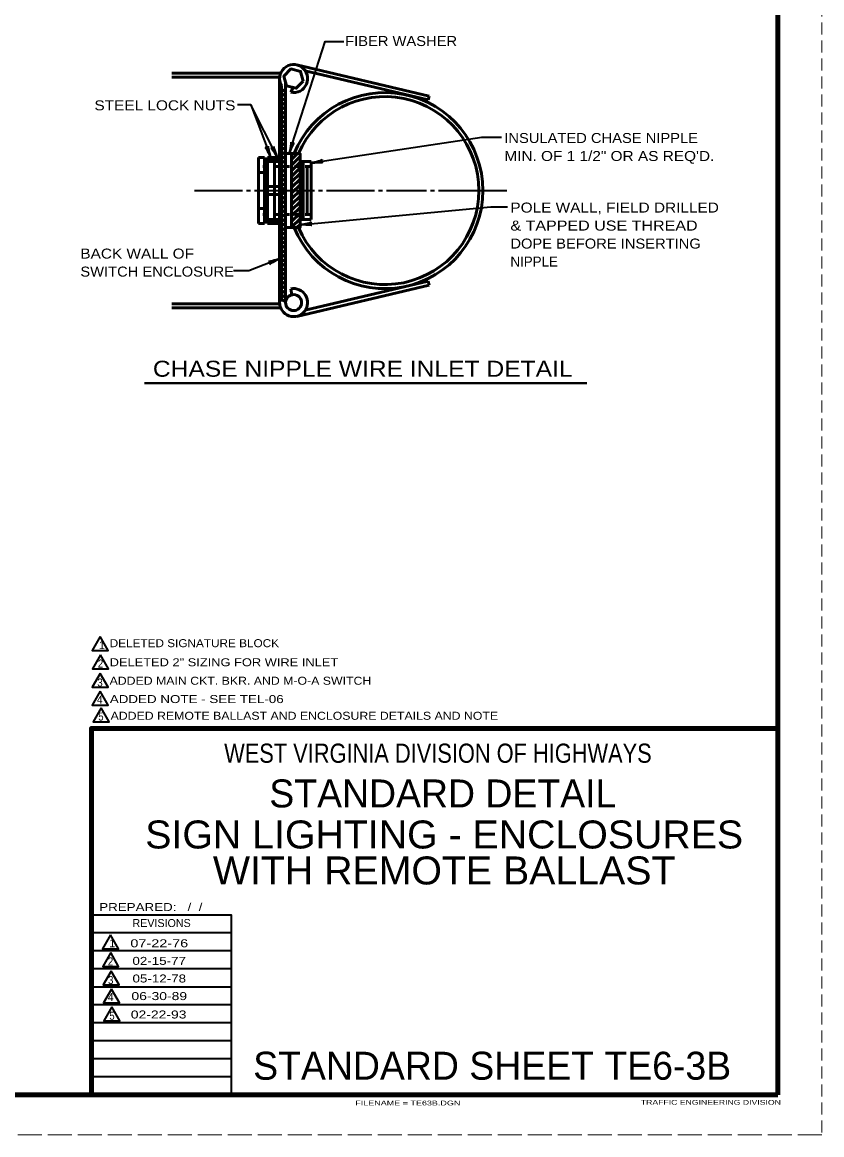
# Model space of a CAD drawing. Extents: x -77 to 603, y -47 to 393.
# Drawn here: x 403.1 to 603.1, y -46.8 to 231.3 of the extents above; entities that cross this region are included whole.
import ezdxf
from ezdxf.enums import TextEntityAlignment as Align

# ---------------------------------------------------------------- set-up
doc = ezdxf.new("R2010")
doc.units = 0
for name, pattern in [('LONG_DASHED', [7.5, 6, -1.5]), ('MEDIUM_DASHED', [4.5, 3, -1.5]), ('SHORT_DASHED', [2.7, 1.5, -1.2])]:
    doc.linetypes.add(name, pattern=pattern)
doc.layers.add('1', color=7, linetype='Continuous', lineweight=53)
doc.layers.add('61', color=7, linetype='Continuous', lineweight=35)

msp = doc.modelspace()

# ---------------------------------------------------------------- linework, layer by layer
at = {"layer": '1', "linetype": 'MEDIUM_DASHED', "lineweight": 13}
msp.add_line((603.055, 393.264), (603.035, -46.756), dxfattribs=at)
at = {"layer": '1'}
for p, q in [((471.839, 220.696), (504.888, 212.859)), ((467.758, 218.556), (440.517, 218.556)), ((467.517, 217.556), (440.517, 217.556)), ((467.502, 217.242), (467.502, 161.242)), ((473.92, 219.174), (504.657, 211.886)), ((467.502, 214.026), (468.002, 214.526)), ((468.002, 215.439), (468.002, 161.977)), ((468.002, 214.526), (469.002, 214.026)), ((469.002, 216.349), (469.002, 161.242)), ((470.283, 213.816), (470.892, 215.033)), ((467.502, 212.93), (468.002, 213.43)), ((467.502, 211.79), (468.002, 212.29)), ((468.002, 213.408), (469.002, 212.908)), ((468.002, 212.29), (469.002, 211.79)), ((504.657, 211.886), (504.888, 212.859)), ((467.502, 210.672), (468.002, 211.172)), ((467.502, 209.554), (468.002, 210.054)), ((467.502, 208.436), (468.002, 208.936)), ((468.002, 211.172), (469.002, 210.672)), ((468.002, 210.054), (469.002, 209.554)), ((468.002, 208.936), (469.002, 208.436)), ((467.502, 207.318), (468.002, 207.818)), ((467.502, 206.2), (468.002, 206.7)), ((468.002, 207.818), (469.002, 207.318)), ((468.002, 206.7), (469.002, 206.2)), ((467.502, 205.082), (468.002, 205.582)), ((467.502, 203.964), (468.002, 204.464)), ((467.502, 202.846), (468.002, 203.346)), ((468.002, 205.582), (469.002, 205.082)), ((468.002, 204.464), (469.002, 203.964)), ((468.002, 203.346), (469.002, 202.845)), ((467.502, 201.727), (468.002, 202.227)), ((467.502, 200.609), (468.002, 201.109)), ((468.002, 202.227), (469.002, 201.727)), ((468.002, 201.109), (469.002, 200.609)), ((462.252, 197.492), (462.252, 180.992)), ((462.252, 197.492), (463.752, 197.492)), ((463.752, 197.492), (463.752, 180.992)), ((467.502, 197.492), (464.502, 197.492)), ((464.502, 197.492), (464.502, 180.992)), ((466.252, 197.492), (466.252, 180.992)), ((467.502, 199.491), (468.002, 199.991)), ((467.502, 198.373), (468.002, 198.873)), ((467.502, 197.255), (468.002, 197.755)), ((468.002, 199.991), (469.002, 199.491)), ((468.002, 198.873), (469.002, 198.373)), ((468.002, 197.755), (469.002, 197.255)), ((470.502, 198.492), (469.002, 198.492)), ((470.502, 198.458), (470.536, 198.492)), ((470.502, 197.044), (471.95, 198.492)), ((470.502, 195.63), (472.627, 197.755)), ((467.502, 196.492), (463.752, 196.492)), ((467.502, 196.992), (464.502, 196.992)), ((467.502, 196.137), (468.002, 196.637)), ((467.502, 195.019), (468.002, 195.519)), ((468.002, 196.637), (469.002, 196.137)), ((468.002, 195.519), (469.002, 195.019)), ((470.502, 194.215), (472.627, 196.34)), ((470.502, 192.801), (472.627, 194.926)), ((475.377, 196.492), (472.627, 196.492)), ((473.377, 196.492), (473.377, 181.992)), ((474.377, 195.242), (474.377, 183.242)), ((475.377, 196.492), (475.377, 181.992)), ((463.752, 193.742), (462.252, 193.742)), ((467.502, 193.901), (468.002, 194.401)), ((467.502, 192.783), (468.002, 193.283)), ((467.502, 191.665), (468.002, 192.165)), ((468.002, 194.401), (469.002, 193.901)), ((468.002, 193.283), (469.002, 192.783)), ((468.002, 192.165), (469.002, 191.665)), ((470.502, 191.387), (472.627, 193.512)), ((470.502, 189.973), (472.627, 192.098)), ((467.502, 190.242), (464.502, 190.242)), ((467.502, 190.547), (468.002, 191.047)), ((467.502, 189.428), (468.002, 189.928)), ((468.002, 191.047), (469.002, 190.546)), ((468.002, 189.928), (469.002, 189.428)), ((470.502, 188.558), (472.627, 190.683)), ((470.502, 187.144), (472.627, 189.269)), ((467.502, 188.242), (464.502, 188.242)), ((467.502, 188.31), (468.002, 188.81)), ((467.502, 187.192), (468.002, 187.692)), ((467.502, 186.074), (468.002, 186.574)), ((468.002, 188.81), (469.002, 188.31)), ((468.002, 187.692), (469.002, 187.192)), ((468.002, 186.574), (469.002, 186.074)), ((470.502, 185.73), (472.627, 187.855)), ((470.502, 184.316), (472.627, 186.441)), ((463.752, 184.742), (462.252, 184.742)), ((467.502, 184.956), (468.002, 185.456)), ((467.502, 183.838), (468.002, 184.338)), ((468.002, 185.456), (469.002, 184.956)), ((468.002, 184.338), (469.002, 183.838)), ((470.502, 182.901), (472.627, 185.026)), ((470.502, 181.487), (472.627, 183.612)), ((462.252, 180.992), (463.752, 180.992)), ((467.502, 181.992), (463.752, 181.992)), ((467.502, 181.492), (464.502, 181.492)), ((467.502, 180.992), (464.502, 180.992)), ((467.502, 182.72), (468.002, 183.22)), ((467.502, 181.602), (468.002, 182.102)), ((467.502, 180.484), (468.002, 180.984)), ((468.002, 183.22), (469.002, 182.72)), ((468.002, 182.102), (469.002, 181.602)), ((468.002, 180.984), (469.002, 180.484)), ((470.502, 180.073), (472.627, 182.198)), ((471.835, 179.992), (472.627, 180.784)), ((475.377, 181.992), (472.627, 181.992)), ((467.502, 179.366), (468.002, 179.866)), ((467.502, 178.248), (468.002, 178.748)), ((468.002, 179.866), (469.002, 179.366)), ((468.002, 178.748), (469.002, 178.248)), ((470.502, 179.992), (469.002, 179.992)), ((467.502, 177.13), (468.002, 177.63)), ((467.502, 176.012), (468.002, 176.512)), ((467.502, 174.893), (468.002, 175.393)), ((468.002, 177.63), (469.002, 177.13)), ((468.002, 176.512), (469.002, 176.011)), ((468.002, 175.393), (469.002, 174.893)), ((467.502, 173.775), (468.002, 174.275)), ((467.502, 172.657), (468.002, 173.157)), ((468.002, 174.275), (469.002, 173.775)), ((468.002, 173.157), (469.002, 172.657)), ((467.502, 171.539), (468.002, 172.039)), ((467.502, 170.421), (468.002, 170.921)), ((467.502, 169.303), (468.002, 169.803)), ((468.002, 172.039), (469.002, 171.539)), ((468.002, 170.921), (469.002, 170.421)), ((468.002, 169.803), (469.002, 169.303)), ((467.502, 168.185), (468.002, 168.685)), ((467.502, 167.067), (468.002, 167.567)), ((468.002, 168.685), (469.002, 168.185)), ((468.002, 167.567), (469.002, 167.067)), ((467.502, 165.949), (468.002, 166.449)), ((467.502, 164.831), (468.002, 165.331)), ((467.502, 163.713), (468.002, 164.213)), ((468.002, 166.449), (469.002, 165.949)), ((468.002, 165.331), (469.002, 164.831)), ((468.002, 164.213), (469.002, 163.713)), ((470.283, 164.667), (470.591, 163.197)), ((471.839, 157.788), (504.888, 165.624)), ((473.92, 159.309), (504.657, 166.597)), ((504.657, 166.597), (504.888, 165.624)), ((467.502, 162.595), (468.002, 163.095)), ((467.502, 161.477), (468.002, 161.977)), ((468.002, 163.095), (469.002, 162.595)), ((468.002, 161.977), (469.002, 161.476)), ((467.517, 160.927), (440.517, 160.927)), ((467.758, 159.927), (440.517, 159.927))]:
    msp.add_line(p, q, dxfattribs=at)
at = {"layer": '1', "lineweight": 35}
for p, q in [((460.33, 210.688), (456.984, 210.688)), ((446.252, 189.242), (458.252, 189.242)), ((459.252, 189.242), (460.252, 189.242)), ((461.252, 189.242), (476.252, 189.242)), ((477.252, 189.242), (478.252, 189.242)), ((479.252, 189.242), (491.252, 189.242)), ((492.252, 189.242), (493.252, 189.242)), ((494.252, 189.242), (504.252, 189.242)), ((505.252, 189.242), (506.252, 189.242)), ((507.252, 189.242), (524.325, 189.242)), ((455.435, 3.664), (420.455, 3.664)), ((455.435, -0.836), (420.455, -0.836)), ((455.435, -5.336), (420.455, -5.336)), ((455.435, -9.856), (420.455, -9.856)), ((455.435, -14.336), (420.455, -14.336)), ((455.435, -18.816), (420.455, -18.816)), ((455.435, -23.316), (420.455, -23.316)), ((455.435, -27.816), (420.455, -27.816)), ((455.435, -32.336), (420.455, -32.336))]:
    msp.add_line(p, q, dxfattribs=at)
at = {"layer": '1', "linetype": 'SHORT_DASHED'}
for p, q in [((467.502, 195.242), (462.252, 195.242)), ((475.377, 195.242), (469.002, 195.242)), ((467.502, 183.242), (462.252, 183.242)), ((475.377, 183.242), (469.002, 183.242))]:
    msp.add_line(p, q, dxfattribs=at)
at = {"layer": '1', "lineweight": 40}
msp.add_line((433.674, 141.075), (544.289, 141.075), dxfattribs=at)
at = {"layer": '1', "lineweight": 35}
for points in [[(469.893, 198.492), (478.882, 226.487), (483.579, 226.487)], [(466.977, 197.492), (460.33, 210.688), (465.281, 197.492)], [(475.377, 196.147), (518.067, 202.582), (522.979, 202.582)], [(472.627, 180.701), (520.289, 185.153), (524.499, 185.153)], [(467.502, 172.204), (459.78, 169.197), (455.931, 169.197)], [(455.435, -36.816), (455.435, 8.144), (420.455, 8.144)]]:
    msp.add_lwpolyline(points, dxfattribs=at)
at = {"layer": '1'}
for points in [[(473.421, 216.61), (472.759, 219.021), (470.34, 219.652), (468.583, 217.873), (469.246, 215.463), (471.665, 214.831)], [(470.502, 179.992), (470.502, 198.492), (472.627, 198.492), (472.627, 179.992)]]:
    msp.add_lwpolyline(points, close=True, dxfattribs=at)
at = {"layer": '1', "lineweight": 35}
for points in [[(422.646, 77.766), (420.646, 74.302), (424.646, 74.302)], [(422.722, 73.181), (420.722, 69.717), (424.722, 69.717)], [(422.658, 68.533), (420.658, 65.069), (424.658, 65.069)], [(422.646, 64.087), (420.646, 60.623), (424.646, 60.623)], [(422.836, 59.913), (420.836, 56.449), (424.836, 56.449)], [(425.21, 3.202), (423.21, -0.262), (427.21, -0.262)], [(425.252, -1.243), (423.252, -4.707), (427.252, -4.707)], [(425.336, -5.86), (423.336, -9.324), (427.336, -9.324)], [(425.464, -10.348), (423.464, -13.813), (427.464, -13.813)], [(425.515, -14.801), (423.515, -18.265), (427.515, -18.265)]]:
    msp.add_lwpolyline(points, close=True, dxfattribs=at)
at = {"layer": '1', "lineweight": 158}
msp.add_lwpolyline([(420.435, -36.776), (420.435, 54.804), (592.095, 54.804)], dxfattribs=at)
at = {"layer": '1'}
for centre, radius, start, end in [((471.002, 217.242), 3.5, 258.13571, 210.93646), ((493.825, 189.242), 24.5, 202.18207, 157.81793), ((493.825, 189.242), 23.5, 203.17975, 156.82025), ((471.002, 161.242), 3.5, 180, 101.86429), ((471.002, 161.242), 1.998, 180, 176.5775)]:
    msp.add_arc(centre, radius, start, end, dxfattribs=at)
at = {"layer": '1', "lineweight": 40}
for centre, major_axis, ratio, start_param, end_param in [((465.086, 198.615), (0.453, -1.706), 0.07063, 3.1407148, 5.41811), ((465.086, 198.615), (0.453, -1.706), 0.07063, 3.1407148, 5.41811), ((466.662, 198.588), (0.633, -1.648), 0.07063, 3.1407148, 5.41811), ((469.964, 199.615), (-0.397, -1.748), 0.122415, 0.8963533, 3.1415927), ((470.437, 199.494), (0.704, 1.619), 0.07063, 6.2823074, 8.5597026), ((464.639, 198.416), (0.773, -1.617), 0.122415, 0.8963533, 3.1415927), ((464.639, 198.416), (0.773, -1.617), 0.122415, 0.8963533, 3.1415927), ((466.24, 198.342), (0.943, -1.525), 0.122415, 0.8963533, 3.1415927), ((476.415, 196.583), (-1.742, -0.421), 0.122415, 0.8963533, 3.1415927), ((476.415, 196.583), (-1.742, -0.421), 0.122415, 0.8963533, 3.1415927), ((476.517, 196.105), (1.763, 0.088), 0.07063, 6.2823074, 8.5597026), ((476.517, 196.105), (1.763, 0.088), 0.07063, 6.2823074, 8.5597026), ((473.688, 181.078), (-1.763, -0.322), 0.122415, 0.8963533, 3.1415927), ((473.688, 181.078), (-1.763, -0.322), 0.122415, 0.8963533, 3.1415927), ((473.763, 180.595), (1.765, -0.012), 0.07063, 6.2823074, 8.5597026), ((473.763, 180.595), (1.765, -0.012), 0.07063, 6.2823074, 8.5597026), ((466.381, 171.995), (1.7, 0.474), 0.07063, 3.1407148, 5.41811), ((466.586, 171.551), (1.607, 0.794), 0.122415, 0.8963533, 3.1415927)]:
    msp.add_ellipse(centre, major_axis=major_axis, ratio=ratio, start_param=start_param, end_param=end_param, dxfattribs=at)
at = {"layer": '61', "lineweight": 158}
for p, q in [((592.075, 383.264), (592.095, -36.776)), ((592.095, -36.776), (-46.965, -36.756))]:
    msp.add_line(p, q, dxfattribs=at)
at = {"layer": '61', "linetype": 'LONG_DASHED', "lineweight": 13}
msp.add_line((603.035, -46.756), (-77.025, -46.776), dxfattribs=at)

# ---------------------------------------------------------------- texts
at = {"layer": '1'}
for s, height, width, p in [('FIBER WASHER', 2.5, 1.1, (497.876, 225.373)), ('STEEL LOCK NUTS', 2.5, 1.15, (438.817, 209.302)), ('CHASE NIPPLE WIRE INLET DETAIL', 4, 1.15, (488.276, 142.707)), ('WEST VIRGINIA DIVISION OF HIGHWAYS', 4.795, 0.85, (507.083, 46.204)), ('SIGN LIGHTING - ENCLOSURES', 6.993, 1.05, (508.647, 24.785)), ('WITH REMOTE BALLAST', 6.993, 1.05, (508.647, 15.792)), ('07-22-76', 2, 1.35, (437.404, 0.084)), ('02-15-77', 2, 1.25, (437.384, -4.316)), ('05-12-78', 2, 1.25, (437.404, -8.716)), ('06-30-89', 2, 1.3, (437.404, -13.116)), ('02-22-93', 2, 1.3, (437.244, -17.716))]:
    msp.add_text(s, height=height, dxfattribs=dict(at, width=width)).set_placement(p, align=Align.CENTER)
for s, height, width, p in [('INSULATED CHASE NIPPLE', 2.5, 1.1, (523.68, 201.135)), ('MIN. OF 1 1/2" OR AS REQ\'D.', 2.5, 1.15, (523.68, 196.635)), ('POLE WALL, FIELD DRILLED', 2.5, 1.15, (525.201, 183.743)), ('& TAPPED USE THREAD', 2.5, 1.2, (525.201, 179.243)), ('DOPE BEFORE INSERTING', 2.5, 1.1, (525.201, 174.743)), ('BACK WALL OF', 2.5, 1.15, (417.673, 172.239)), ('SWITCH ENCLOSURE', 2.5, 1.1, (417.673, 167.739)), ('DELETED SIGNATURE BLOCK', 2, 1.1, (425.009, 75.104)), ('DELETED 2" SIZING FOR WIRE INLET', 2, 1.2, (425.009, 70.33)), ('2', 2, 0.9, (422.05, 70.012)), ('3', 2, 0.9, (421.923, 65.269)), ('ADDED MAIN CKT. BKR. AND M-O-A SWITCH', 2, 1.15, (424.977, 65.715)), ('4', 2, 0.95, (421.827, 61.004)), ('ADDED NOTE - SEE TEL-06', 2, 1.25, (425.041, 61.132)), ('5', 2, 0.9, (422.145, 56.766)), ('ADDED REMOTE BALLAST AND ENCLOSURE DETAILS AND NOTE', 2, 1.15, (425.23, 56.957)), ('PREPARED:   /  /  ', 1.998, 1.25, (422.395, 9.144)), ('2', 2, 0.9, (424.557, -4.447)), ('3', 2, 0.9, (424.6, -9.102)), ('4', 2, 0.95, (424.557, -13.369)), ('5', 2, 0.9, (424.911, -18.024)), ('FILENAME = TE63B.DGN', 1.2, 1.4, (486.414, -39.447)), ('TRAFFIC ENGINEERING DIVISION', 1.2, 1.35, (557.815, -39.276))]:
    msp.add_text(s, height=height, dxfattribs=dict(at, width=width)).set_placement(p)
for s, height, p in [('NIPPLE', 2.5, (525.201, 170.243)), ('1', 2, (422.336, 74.627)), ('REVISIONS', 1.998, (430.715, 5.144)), ('1', 2, (424.901, 0.079))]:
    msp.add_text(s, height=height, dxfattribs=at).set_placement(p)
for s, p in [('STANDARD DETAIL', (508.305, 35.044)), ('STANDARD SHEET TE6-3B', (520.645, -33.016))]:
    msp.add_text(s, height=6.993, dxfattribs=at).set_placement(p, align=Align.CENTER)

doc.saveas('drawing.dxf')
